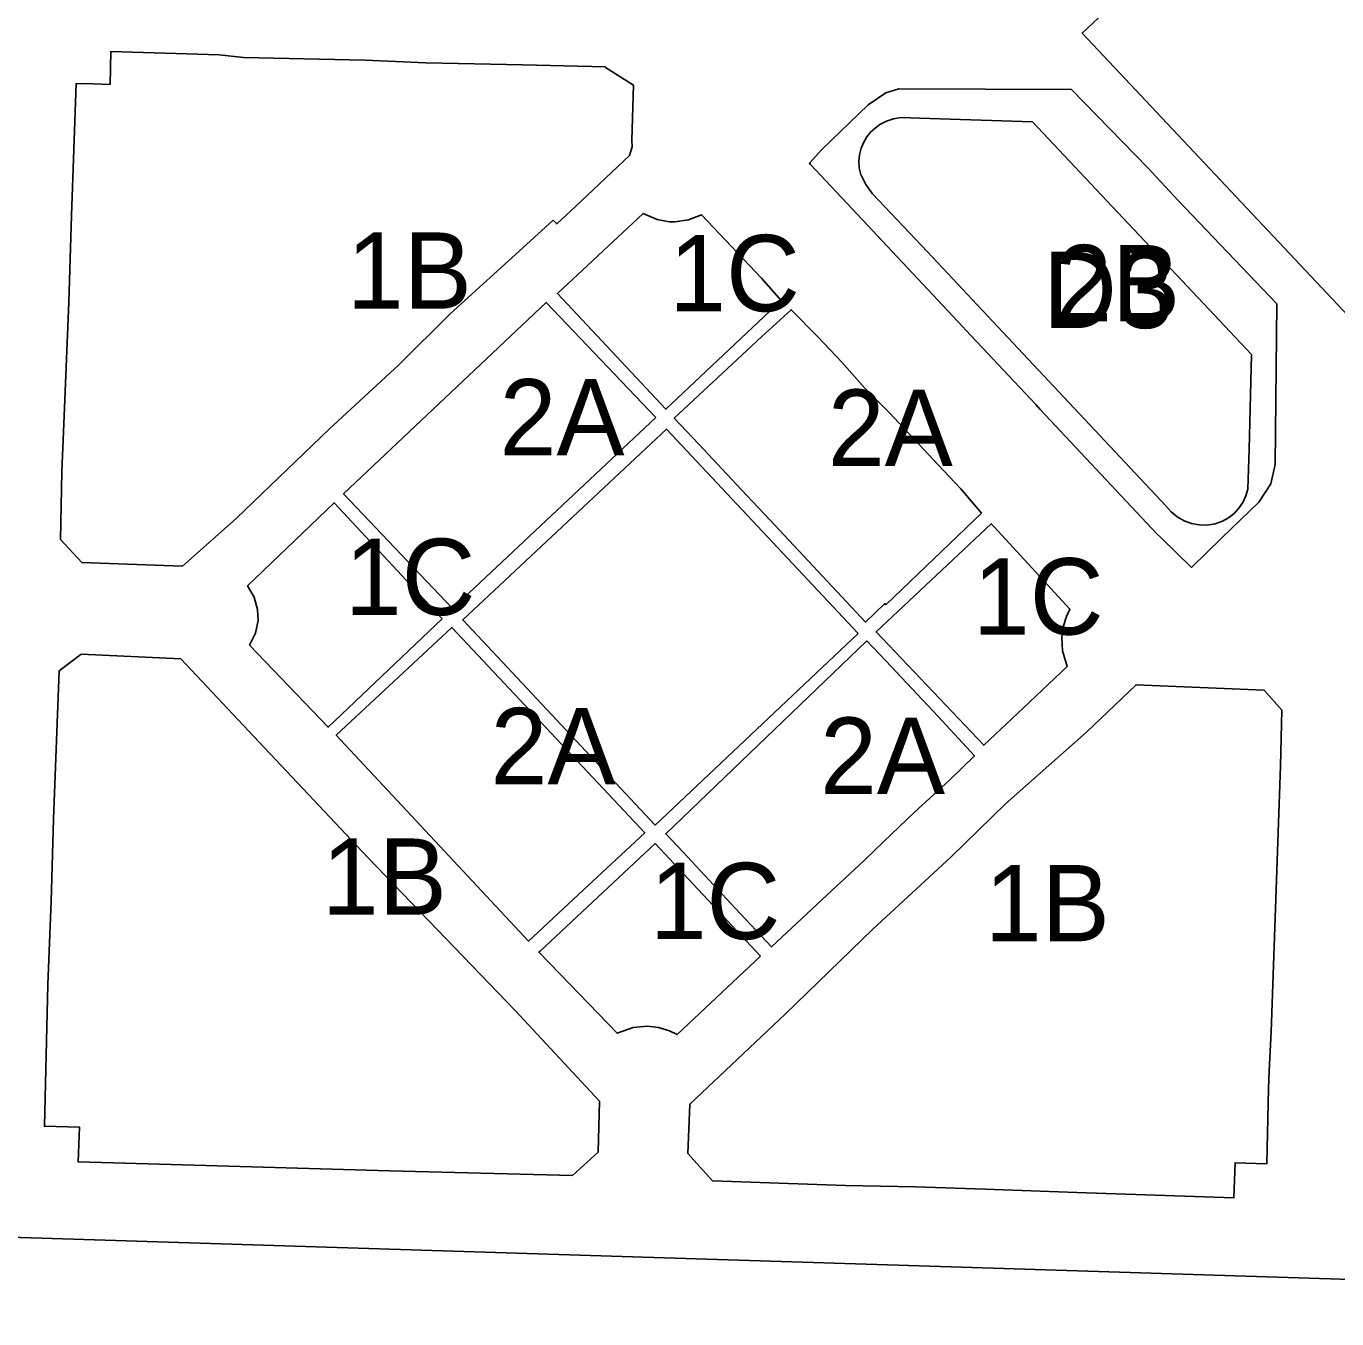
# Model space of a CAD drawing. Extents: x 598968 to 613553, y 4409678 to 4430833.
# Drawn here: x 607191.8 to 607397.8, y 4414877.8 to 4415081 of the extents above; entities that cross this region are included whole.
import ezdxf

# ---------------------------------------------------------------- set-up
doc = ezdxf.new("R2010")
doc.units = 0
for name, color, linetype in [('1', 7, 'Continuous'), ('Sòl Rústic Comú', 7, 'Continuous'), ('ZONA 1B. Illes de cases extensives - ANNEX III C', 7, 'Continuous'), ('ZONA 1C. Cases aïllades centrals - ANNEX III C', 7, 'Continuous'), ('ZONA 2A. Fileres de cases - ANNEX III C', 7, 'Continuous'), ('ZONA 2B. Blocs aïllats - ANNEX III C', 7, 'Continuous'), ('ZONES URBANES. Espai lliure privat', 7, 'Continuous')]:
    doc.layers.add(name, color=color, linetype=linetype)

msp = doc.modelspace()

# ---------------------------------------------------------------- linework, layer by layer
at = {"layer": '1'}
msp.add_lwpolyline([(607188.9854, 4415307.5895), (607187.6479, 4415265.1867), (607187.498, 4415260.3611), (607187.4972, 4415260.3567), (607187.5738, 4415260.3543), (607184.3641, 4415157.1073), (607181.1888, 4415053.379), (607179.389, 4414994.4797), (607161.42, 4414994.3905), (607161.3258, 4414994.3939), (607161.1496, 4414988.3133), (607161.2899, 4414988.3072), (607179.719, 4414987.7597), (607176.3789, 4414882.269), (607176.297, 4414881.0231), (607181.9406, 4414879.966), (607182.6109, 4414890.8858), (607290.4887, 4414887.464), (607335.4954, 4414886.0365), (607419.8931, 4414883.3596), (607565.895, 4414878.7285), (607599.3601, 4414877.8385), (607611.7702, 4414878.0005)], dxfattribs=at)
for points in [[(607406.2436, 4415028.3837), (607357.7665, 4415079.882), (607400.0659, 4415119.5323), (607448.0291, 4415068.3834), (607494.246, 4415066.8294), (607500.435, 4415062.8748), (607499.825, 4415051.5949), (607498.0651, 4415043.685), (607491.9652, 4415032.845), (607490.0452, 4415030.475), (607482.0353, 4415016.935), (607480.3354, 4415012.755), (607477.1754, 4415002.7051), (607475.9355, 4414997.5151), (607474.8055, 4414990.8552), (607474.0155, 4414988.7052), (607472.5456, 4414987.3552), (607471.0256, 4414986.6852), (607467.1856, 4414986.4151), (607404.8763, 4414988.4539)], [(607448.0291, 4415068.3834), (607400.0659, 4415119.5323), (607357.7665, 4415079.882), (607406.2436, 4415028.3837), (607406.4361, 4415034.0034), (607442.4385, 4415068.5714)], [(607282.8624, 4415074.4972), (607287.2523, 4415071.7273), (607287.0304, 4415063.0717), (607287.0524, 4415061.9874), (607286.6524, 4415060.6674), (607278.0951, 4415052.5834), (607275.2026, 4415049.8873), (607274.651, 4415050.4692), (607270.4426, 4415046.6773), (607258.4829, 4415035.7814), (607250.3929, 4415027.7471), (607239.4535, 4415017.657), (607224.8233, 4415003.6269), (607216.3935, 4414996.1268), (607200.5585, 4414996.6867), (607197.2337, 4415000.2864), (607197.4578, 4415010.9508), (607197.9486, 4415023.5462), (607198.5454, 4415037.6118), (607198.9635, 4415051.1959), (607199.6834, 4415071.9657), (607202.3484, 4415071.8957), (607205.0133, 4415071.8258), (607205.1433, 4415077.0157), (607222.1631, 4415076.496), (607225.9731, 4415076.0261), (607245.1128, 4415075.6165), (607254.6427, 4415075.2266), (607269.8985, 4415074.8964), (607282.8624, 4415074.5972)], [(607356.1102, 4415071.031), (607368.07, 4415058.7217), (607372.8799, 4415053.6021), (607388.3597, 4415037.3329), (607388.1199, 4415012.0735), (607387.4299, 4415009.0737), (607385.5199, 4415006.1737), (607379.7301, 4415000.5435), (607374.9803, 4414995.9135), (607370.1804, 4415000.5431), (607369.5105, 4415001.1931), (607351.1707, 4415020.752), (607350.4707, 4415021.5019), (607339.4909, 4415033.2013), (607339.0209, 4415033.7013), (607320.0612, 4415053.9201), (607319.9512, 4415054.0301), (607315.0413, 4415059.2697), (607314.9013, 4415059.4197), (607316.8412, 4415061.5897), (607324.121, 4415068.6099), (607326.9209, 4415070.5199), (607328.9709, 4415071.14)], [(607292.8923, 4415050.2376), (607293.7723, 4415050.2177), (607295.9223, 4415050.5427), (607297.9523, 4415051.3477), (607307.3722, 4415041.368), (607310.4821, 4415037.8581), (607292.3625, 4415020.778), (607275.3026, 4415038.9874), (607288.7724, 4415051.5575), (607290.9852, 4415050.5863)], [(607290.7525, 4415019.4979), (607258.803, 4414989.4477), (607241.7231, 4415007.4872), (607273.5545, 4415037.567)], [(607341.9519, 4415004.4691), (607326.9421, 4414990.059), (607326.7621, 4414990.2389), (607323.7522, 4414987.3389), (607320.0222, 4414991.3088), (607316.2422, 4414995.3287), (607312.4622, 4414999.3686), (607308.6923, 4415003.3785), (607305.0424, 4415007.2684), (607301.1924, 4415011.3682), (607297.5124, 4415015.2981), (607293.6724, 4415019.388), (607302.7823, 4415027.8581), (607307.4122, 4415032.2181), (607312.0221, 4415036.3981), (607316.2521, 4415032.1583), (607319.9921, 4415028.1784), (607323.572, 4415024.1585), (607327.472, 4415020.2186), (607331.212, 4415016.2387), (607335.9919, 4415011.1589), (607338.7019, 4415008.279)], [(607322.5694, 4414985.5324), (607290.6699, 4414955.4319), (607260.4302, 4414987.6641), (607292.4652, 4415017.6185)], [(607322.5694, 4414985.5324), (607292.4652, 4415017.6185), (607260.4302, 4414987.6641), (607290.6699, 4414955.4319)], [(607257.223, 4414987.8177), (607239.2862, 4414970.7924), (607226.9334, 4414983.6972), (607227.8534, 4414985.5672), (607228.2751, 4414987.5596), (607228.1833, 4414989.2821), (607227.6333, 4414991.2471), (607226.6034, 4414993.0071), (607240.2231, 4415006.0772)], [(607348.5419, 4414973.8495), (607342.302, 4414967.9595), (607325.3921, 4414985.769), (607343.4819, 4415002.7791), (607343.9199, 4415002.3043), (607355.8518, 4414989.3695), (607355.3118, 4414988.2045), (607354.8018, 4414986.5845), (607354.5768, 4414984.8945), (607354.6752, 4414982.8259), (607355.4018, 4414980.3296)], [(607279.3335, 4414945.1781), (607270.7454, 4414937.1957), (607240.5708, 4414969.5447), (607258.7078, 4414986.4682), (607289.0672, 4414954.2188)], [(607318.44, 4414945.1465), (607308.9451, 4414936.2795), (607303.2326, 4414942.3691), (607295.0527, 4414951.1488), (607292.3327, 4414954.0687), (607323.9322, 4414984.379), (607326.9421, 4414981.2391), (607335.1321, 4414972.4693), (607340.8503, 4414966.2894), (607336.9109, 4414962.4819), (607331.3773, 4414957.3772), (607326.6049, 4414952.8244), (607323.4897, 4414949.832)], [(607281.713, 4414904.0391), (607277.6631, 4414900.3691), (607248.9234, 4414901.0985), (607216.4338, 4414902.0179), (607199.9831, 4414902.4985), (607200.204, 4414907.9575), (607194.6904, 4414908.0852), (607195.214, 4414930.3572), (607195.7536, 4414943.4825), (607196.1439, 4414956.3569), (607197.0238, 4414979.6467), (607200.4637, 4414982.2867), (607216.1435, 4414981.537), (607228.4201, 4414968.4574), (607245.5033, 4414950.3079), (607268.6481, 4414926.3036), (607281.943, 4414912.029)], [(607387.0417, 4414914.0209), (607386.8017, 4414902.2011), (607381.8118, 4414902.371), (607381.6218, 4414896.841), (607356.9421, 4414897.6906), (607342.5422, 4414898.1903), (607331.6024, 4414898.5701), (607320.5625, 4414898.7899), (607299.6604, 4414899.5328), (607295.8128, 4414903.7894), (607296.1028, 4414911.5693), (607311.0913, 4414925.7283), (607324.8623, 4414939.0895), (607337.1821, 4414950.4296), (607345.702, 4414958.7697), (607358.4518, 4414970.0498), (607366.2517, 4414977.4798), (607386.3514, 4414976.6202), (607389.1635, 4414973.4987), (607388.9353, 4414964.7439), (607387.452, 4414922.9086), (607387.1666, 4414916.8309)], [(607307.2226, 4414934.8392), (607294.1428, 4414922.4891), (607292.9378, 4414923.0841), (607291.2228, 4414923.6191), (607289.4428, 4414923.819), (607287.2129, 4414923.619), (607284.7204, 4414922.7019), (607275.7258, 4414932.0056), (607272.4151, 4414935.4428), (607272.583, 4414935.5986), (607290.6649, 4414952.5089)]]:
    msp.add_lwpolyline(points, close=True, dxfattribs=at)
at = {"layer": 'Sòl Rústic Comú'}
msp.add_lwpolyline([(607611.7702, 4414878.0005), (607599.3601, 4414877.8385), (607565.895, 4414878.7285), (607419.8931, 4414883.3596), (607335.4954, 4414886.0365), (607290.4887, 4414887.464), (607182.6109, 4414890.8858)], dxfattribs=at)
at = {"layer": 'ZONA 1B. Illes de cases extensives - ANNEX III C'}
for points in [[(607282.8624, 4415074.4972), (607282.8624, 4415074.5972), (607269.8985, 4415074.8964), (607254.6427, 4415075.2266), (607245.1128, 4415075.6165), (607225.9731, 4415076.0261), (607222.1631, 4415076.496), (607205.1433, 4415077.0157), (607205.0133, 4415071.8258), (607202.3484, 4415071.8957), (607199.6834, 4415071.9657), (607198.9635, 4415051.1959), (607198.5454, 4415037.6118), (607197.9486, 4415023.5462), (607197.4578, 4415010.9508), (607197.2337, 4415000.2864), (607200.5585, 4414996.6867), (607216.3935, 4414996.1268), (607224.8233, 4415003.6269), (607239.4535, 4415017.657), (607250.3929, 4415027.7471), (607258.4829, 4415035.7814), (607270.4426, 4415046.6773), (607274.651, 4415050.4692), (607275.2026, 4415049.8873), (607278.0951, 4415052.5834), (607286.6524, 4415060.6674), (607287.0524, 4415061.9874), (607287.0304, 4415063.0717), (607287.2523, 4415071.7273)], [(607281.713, 4414904.0391), (607281.943, 4414912.029), (607268.6481, 4414926.3036), (607245.5033, 4414950.3079), (607228.4201, 4414968.4574), (607216.1435, 4414981.537), (607200.4637, 4414982.2867), (607197.0238, 4414979.6467), (607196.1439, 4414956.3569), (607195.7536, 4414943.4825), (607195.214, 4414930.3572), (607194.6904, 4414908.0852), (607200.204, 4414907.9575), (607199.9831, 4414902.4985), (607216.4338, 4414902.0179), (607248.9234, 4414901.0985), (607277.6631, 4414900.3691)], [(607387.0417, 4414914.0209), (607387.1666, 4414916.8309), (607387.452, 4414922.9086), (607388.9353, 4414964.7439), (607389.1635, 4414973.4987), (607386.3514, 4414976.6202), (607366.2517, 4414977.4798), (607358.4518, 4414970.0498), (607345.702, 4414958.7697), (607337.1821, 4414950.4296), (607324.8623, 4414939.0895), (607311.0913, 4414925.7283), (607296.1028, 4414911.5693), (607295.8128, 4414903.7894), (607299.6604, 4414899.5328), (607320.5625, 4414898.7899), (607331.6024, 4414898.5701), (607342.5422, 4414898.1903), (607356.9421, 4414897.6906), (607381.6218, 4414896.841), (607381.8118, 4414902.371), (607386.8017, 4414902.2011)]]:
    msp.add_lwpolyline(points, close=True, dxfattribs=at)
at = {"layer": 'ZONA 1C. Cases aïllades centrals - ANNEX III C'}
for points in [[(607292.8923, 4415050.2376), (607290.9852, 4415050.5863), (607288.7724, 4415051.5575), (607275.3026, 4415038.9874), (607292.3625, 4415020.778), (607310.4821, 4415037.8581), (607307.3722, 4415041.368), (607297.9523, 4415051.3477), (607295.9223, 4415050.5427), (607293.7723, 4415050.2177)], [(607257.223, 4414987.8177), (607240.2231, 4415006.0772), (607226.6034, 4414993.0071), (607227.6333, 4414991.2471), (607228.1833, 4414989.2821), (607228.2751, 4414987.5596), (607227.8534, 4414985.5672), (607226.9334, 4414983.6972), (607239.2862, 4414970.7924)], [(607348.5419, 4414973.8495), (607355.4018, 4414980.3296), (607354.6752, 4414982.8259), (607354.5768, 4414984.8945), (607354.8018, 4414986.5845), (607355.3118, 4414988.2045), (607355.8518, 4414989.3695), (607343.9199, 4415002.3043), (607343.4819, 4415002.7791), (607325.3921, 4414985.769), (607342.302, 4414967.9595)], [(607307.2226, 4414934.8392), (607290.6649, 4414952.5089), (607272.583, 4414935.5986), (607272.4151, 4414935.4428), (607275.7258, 4414932.0056), (607284.7204, 4414922.7019), (607287.2129, 4414923.619), (607289.4428, 4414923.819), (607291.2228, 4414923.6191), (607292.9378, 4414923.0841), (607294.1428, 4414922.4891)]]:
    msp.add_lwpolyline(points, close=True, dxfattribs=at)
at = {"layer": 'ZONA 2A. Fileres de cases - ANNEX III C'}
for points in [[(607290.7525, 4415019.4979), (607273.5545, 4415037.567), (607241.7231, 4415007.4872), (607258.803, 4414989.4477)], [(607341.9519, 4415004.4691), (607338.7019, 4415008.279), (607335.9919, 4415011.1589), (607331.212, 4415016.2387), (607327.472, 4415020.2186), (607323.572, 4415024.1585), (607319.9921, 4415028.1784), (607316.2521, 4415032.1583), (607312.0221, 4415036.3981), (607307.4122, 4415032.2181), (607302.7823, 4415027.8581), (607293.6724, 4415019.388), (607297.5124, 4415015.2981), (607301.1924, 4415011.3682), (607305.0424, 4415007.2684), (607308.6923, 4415003.3785), (607312.4622, 4414999.3686), (607316.2422, 4414995.3287), (607320.0222, 4414991.3088), (607323.7522, 4414987.3389), (607326.7621, 4414990.2389), (607326.9421, 4414990.059)], [(607279.3335, 4414945.1781), (607289.0672, 4414954.2188), (607258.7078, 4414986.4682), (607240.5708, 4414969.5447), (607270.7454, 4414937.1957)], [(607318.44, 4414945.1465), (607323.4897, 4414949.832), (607326.6049, 4414952.8244), (607331.3773, 4414957.3772), (607336.9109, 4414962.4819), (607340.8503, 4414966.2894), (607335.1321, 4414972.4693), (607326.9421, 4414981.2391), (607323.9322, 4414984.379), (607292.3327, 4414954.0687), (607295.0527, 4414951.1488), (607303.2326, 4414942.3691), (607308.9451, 4414936.2795)]]:
    msp.add_lwpolyline(points, close=True, dxfattribs=at)
at = {"layer": 'ZONA 2B. Blocs aïllats - ANNEX III C'}
msp.add_lwpolyline([(607378.6486, 4415002.7816), (607379.8214, 4415003.1898), (607380.7874, 4415003.7299), (607381.6576, 4415004.4137), (607382.4108, 4415005.2246), (607383.0285, 4415006.1429), (607383.4959, 4415007.1461), (607383.8014, 4415008.2098), (607384.0213, 4415014.5197), (607384.3813, 4415029.3696), (607354.9665, 4415060.6487), (607349.9916, 4415065.9285), (607332.1918, 4415066.5132), (607329.2618, 4415066.6081), (607328.1181, 4415066.4267), (607327.0186, 4415066.0636), (607325.9918, 4415065.5281), (607325.2206, 4415064.9717), (607324.5334, 4415064.3142), (607323.9434, 4415063.5683), (607323.4619, 4415062.7481), (607323.0512, 4415061.789), (607322.7926, 4415060.7782), (607322.6923, 4415059.7397), (607322.7525, 4415058.6981), (607322.9719, 4415057.6781), (607323.7747, 4415056.0796), (607324.8269, 4415054.6332), (607333.4685, 4415045.5143), (607343.6625, 4415034.6389), (607370.9415, 4415005.5696), (607371.753, 4415004.6295), (607372.7122, 4415003.8408), (607373.7914, 4415003.2264), (607374.9592, 4415002.8039), (607376.1817, 4415002.5857), (607377.4236, 4415002.5782)], close=True, dxfattribs=at)
at = {"layer": 'ZONES URBANES. Espai lliure privat'}
for points in [[(607356.1102, 4415071.031), (607328.9709, 4415071.14), (607326.9209, 4415070.5199), (607324.121, 4415068.6099), (607316.8412, 4415061.5897), (607314.9013, 4415059.4197), (607315.0413, 4415059.2697), (607319.9512, 4415054.0301), (607320.0612, 4415053.9201), (607339.0209, 4415033.7013), (607339.4909, 4415033.2013), (607350.4707, 4415021.5019), (607351.1707, 4415020.752), (607369.5105, 4415001.1931), (607370.1804, 4415000.5431), (607374.9803, 4414995.9135), (607379.7301, 4415000.5435), (607385.5199, 4415006.1737), (607387.4299, 4415009.0737), (607388.1199, 4415012.0735), (607388.3597, 4415037.3329), (607372.8799, 4415053.6021), (607368.07, 4415058.7217)], [(607378.6486, 4415002.7816), (607377.4236, 4415002.5782), (607376.1817, 4415002.5857), (607374.9592, 4415002.8039), (607373.7914, 4415003.2264), (607372.7122, 4415003.8408), (607371.753, 4415004.6295), (607370.9415, 4415005.5696), (607343.6625, 4415034.6389), (607333.4685, 4415045.5143), (607324.8269, 4415054.6332), (607323.7747, 4415056.0796), (607322.9719, 4415057.6781), (607322.7525, 4415058.6981), (607322.6923, 4415059.7397), (607322.7926, 4415060.7782), (607323.0512, 4415061.789), (607323.4619, 4415062.7481), (607323.9434, 4415063.5683), (607324.5334, 4415064.3142), (607325.2206, 4415064.9717), (607325.9918, 4415065.5281), (607327.0186, 4415066.0636), (607328.1181, 4415066.4267), (607329.2618, 4415066.6081), (607332.1918, 4415066.5132), (607349.9916, 4415065.9285), (607354.9665, 4415060.6487), (607384.3813, 4415029.3696), (607384.0213, 4415014.5197), (607383.8014, 4415008.2098), (607383.4959, 4415007.1461), (607383.0285, 4415006.1429), (607382.4108, 4415005.2246), (607381.6576, 4415004.4137), (607380.7874, 4415003.7299), (607379.8214, 4415003.1898)]]:
    msp.add_lwpolyline(points, close=True, dxfattribs=at)

# ---------------------------------------------------------------- texts
at = {"layer": 'ZONA 1B. Illes de cases extensives - ANNEX III C'}
for p in [(607242.243, 4415036.5713), (607238.3167, 4414941.3279), (607342.4882, 4414937.1604)]:
    msp.add_text('1B', height=12, dxfattribs=at).set_placement(p)
at = {"layer": 'ZONA 1C. Cases aïllades centrals - ANNEX III C'}
for p in [(607292.8923, 4415036.1678), (607241.9132, 4414988.4348), (607340.622, 4414985.3693), (607289.8188, 4414937.499)]:
    msp.add_text('1C', height=12, dxfattribs=at).set_placement(p)
at = {"layer": 'ZONA 2A. Fileres de cases - ANNEX III C'}
for p in [(607266.2378, 4415013.5073), (607317.8121, 4415011.8685), (607264.819, 4414961.832), (607316.5915, 4414960.3293)]:
    msp.add_text('2A', height=12, dxfattribs=at).set_placement(p)
at = {"layer": 'ZONA 2B. Blocs aïllats - ANNEX III C'}
msp.add_text('2B', height=12, dxfattribs=at).set_placement((607353.5368, 4415034.5932))
at = {"layer": 'ZONES URBANES. Espai lliure privat'}
msp.add_text('D3', height=12, dxfattribs=at).set_placement((607351.6305, 4415033.5268))

doc.saveas('drawing.dxf')
